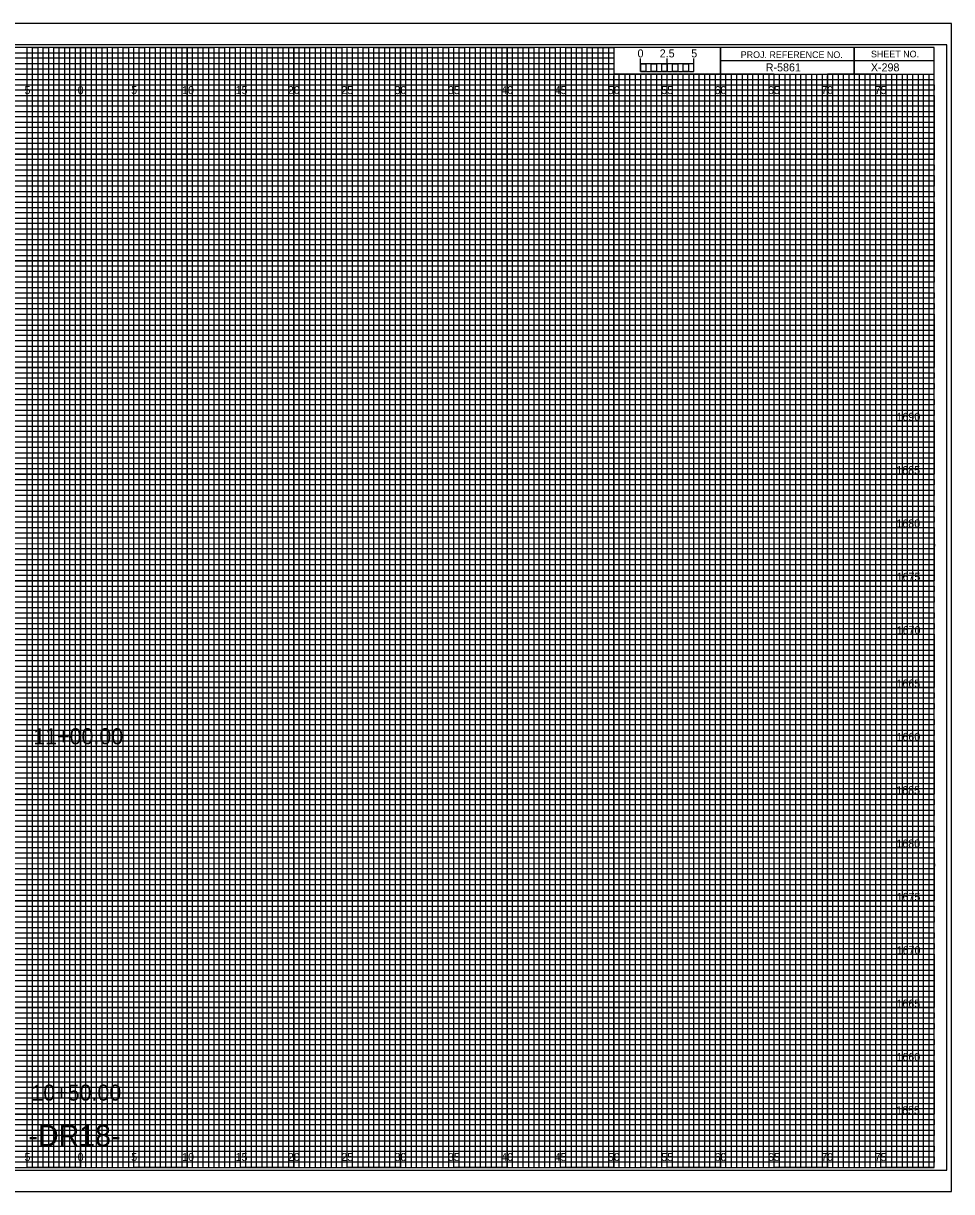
# Model space of a CAD drawing. Extents: x -7 to 162, y -2 to 107.
# Drawn here: x 74.6 to 161.7, y -2.3 to 107.3 of the extents above; entities that cross this region are included whole.
import ezdxf

# ---------------------------------------------------------------- set-up
doc = ezdxf.new("R2010")
doc.units = 0
for name, color, linetype in [('Prop Horizontal Alignment', 7, 'Continuous'), ('Prop XS Alignment Label', 7, 'Continuous'), ('Prop XS Bar Scale Labels', 7, 'Continuous'), ('Prop XS Project Number', 7, 'Continuous'), ('Prop XS Sheet Number', 7, 'Continuous'), ('Raster_Level_0', 7, 'Continuous'), ('Scratch_Level_3', 7, 'Continuous'), ('Sheet Cross Section CELL', 7, 'Continuous'), ('Sheet Cross Section Grid Major CELL', 7, 'Continuous'), ('Sheet Cross Section Grid Middle CELL', 7, 'Continuous'), ('Sheet Cross Section Grid Minor 1 CELL', 7, 'Continuous'), ('Sheet Cross Section Grid Minor 2 CELL', 7, 'Continuous'), ('Sheet Cross Section Scale CELL', 7, 'Continuous'), ('Sheet Cutting Line CELL', 7, 'Continuous'), ('Sheet DOT Grid CELL', 7, 'Continuous'), ('Sheet Plot Border Inside CELL', 7, 'Continuous'), ('Sheet Plot Border Outside CELL', 7, 'Continuous')]:
    doc.layers.add(name, color=color, linetype=linetype)

msp = doc.modelspace()

# ---------------------------------------------------------------- linework, layer by layer
at = {"layer": 'Sheet Cross Section CELL'}
for p, q in [((152.5, 105), (152.5, 102.5)), ((152.5, 102.5), (152.5, 105)), ((160, 103.75), (140, 103.75)), ((140, 103.75), (140, 102.5)), ((140, 102.5), (160, 102.5))]:
    msp.add_line(p, q, dxfattribs=at)
for points in [[(160, 105), (0, 105), (0, 0), (160, 0)], [(140, 105), (130, 105), (130, 102.52), (140, 102.52)], [(160, 105), (140, 105), (140, 102.5), (160, 102.5)]]:
    msp.add_lwpolyline(points, close=True, dxfattribs=at)
at = {"layer": 'Sheet Cross Section Grid Major CELL'}
for p, q in [((75, 105), (70, 105)), ((75, 0), (75, 105)), ((85, 105), (80, 105)), ((80, 105), (80, 0)), ((85, 0), (85, 105)), ((95, 105), (90, 105)), ((90, 105), (90, 0)), ((95, 0), (95, 105)), ((105, 105), (100, 105)), ((100, 105), (100, 0)), ((105, 0), (105, 105)), ((115, 105), (110, 105)), ((110, 105), (110, 0)), ((115, 0), (115, 105)), ((125, 105), (120, 105)), ((120, 105), (120, 0)), ((125, 0), (125, 105)), ((130, 105), (130, 0)), ((135, 0), (135, 102.5)), ((145, 102.5), (140, 102.5)), ((140, 102.5), (140, 0)), ((145, 0), (145, 102.5)), ((155, 102.5), (150, 102.5)), ((150, 102.5), (150, 0)), ((155, 0), (155, 102.5)), ((80, 0), (75, 0)), ((90, 0), (85, 0)), ((100, 0), (95, 0)), ((110, 0), (105, 0)), ((120, 0), (115, 0)), ((130, 0), (125, 0)), ((140, 0), (135, 0)), ((150, 0), (145, 0)), ((160, 0), (155, 0)), ((160, 0), (160, 0))]:
    msp.add_line(p, q, dxfattribs=at)
for points in [[(0, 100), (160, 100), (160, 95), (0, 95)], [(0, 90), (160, 90), (160, 85), (0, 85)], [(0, 80), (160, 80), (160, 75), (0, 75)], [(0, 70), (160, 70), (160, 65), (0, 65)], [(0, 60), (160, 60), (160, 55), (0, 55)], [(0, 50), (160, 50), (160, 45), (0, 45)], [(0, 40), (160, 40), (160, 35), (0, 35)], [(0, 30), (160, 30), (160, 25), (0, 25)], [(0, 20), (160, 20), (160, 15), (0, 15)], [(0, 10), (160, 10), (160, 5), (0, 5)]]:
    msp.add_lwpolyline(points, dxfattribs=at)
at = {"layer": 'Sheet Cross Section Grid Middle CELL'}
for points in [[(72.5, 0), (77.5, 0), (77.5, 105), (82.5, 105), (82.5, 0), (87.5, 0), (87.5, 105), (92.5, 105), (92.5, 0), (97.5, 0), (97.5, 105), (102.5, 105), (102.5, 0), (107.5, 0), (107.5, 105), (112.5, 105), (112.5, 0), (117.5, 0), (117.5, 105), (122.5, 105), (122.5, 0), (127.5, 0), (127.5, 105), (129.97, 105), (130, 105), (130, 102.5), (132.5, 102.5), (132.5, 0), (137.5, 0), (137.5, 102.5), (142.5, 102.5), (142.5, 0), (147.5, 0), (147.5, 102.5), (152.5, 102.5), (152.5, 0), (157.5, 0), (157.5, 102.5)], [(0, 102.5), (137.5, 102.5)], [(0, 92.5), (160, 92.5), (160, 97.5), (0, 97.5)], [(0, 82.5), (160, 82.5), (160, 87.5), (0, 87.5)], [(0, 72.5), (160, 72.5), (160, 77.5), (0, 77.5)], [(0, 62.5), (160, 62.5), (160, 67.5), (0, 67.5)], [(0, 52.5), (160, 52.5), (160, 57.5), (0, 57.5)], [(0, 42.5), (160, 42.5), (160, 47.5), (0, 47.5)], [(0, 32.5), (160, 32.5), (160, 37.5), (0, 37.5)], [(0, 22.5), (160, 22.5), (160, 27.5), (0, 27.5)], [(0, 12.5), (160, 12.5), (160, 17.5), (0, 17.5)], [(0, 2.5), (160, 2.5), (160, 7.5), (0, 7.5)]]:
    msp.add_lwpolyline(points, dxfattribs=at)
at = {"layer": 'Sheet Cross Section Grid Minor 1 CELL'}
for p, q in [((0, 104.5), (130, 104.5)), ((130, 104.5), (130, 103.99)), ((130, 103.99), (0, 103.99)), ((0, 103.5), (130, 103.5)), ((130, 102.95), (0, 102.95)), ((130, 103.5), (130, 102.95)), ((0, 102), (160, 102))]:
    msp.add_line(p, q, dxfattribs=at)
for points in [[(0, 101.5), (135, 101.5), (160, 101.5), (160, 101), (0, 101)], [(0, 100.5), (160, 100.5), (160, 99.5), (0, 99.5)], [(0, 99), (160, 99), (160, 98.5), (0, 98.49)], [(0, 98), (160, 98), (160, 97), (0, 97)], [(0, 96.5), (160, 96.5), (160, 96), (0, 96)], [(0, 95.5), (160, 95.5), (160, 94.5), (0, 94.5)], [(0, 94), (160, 94), (160, 93.5), (0, 93.5)], [(0, 93), (160, 93), (160, 92), (0, 92)], [(0, 91.5), (160, 91.5), (160, 91), (0, 91)], [(0, 90.5), (160, 90.5), (160, 89.5), (0, 89.5)], [(0, 89), (160, 89), (160, 88.5), (0, 88.5)], [(0, 88), (160, 88), (160, 86.98), (160, 86.5), (160, 86), (0, 86)], [(0, 87), (160, 87), (160, 86.5), (0, 86.5)], [(0, 85.5), (160, 85.5), (160, 84.5), (0, 84.52)], [(0, 84.52), (160, 84.5), (160, 84), (0, 84)], [(0, 83.5), (160, 83.5), (160, 83), (0, 83)], [(0, 82), (160, 82), (160, 81.5), (0, 81.5)], [(0, 81), (160, 81), (160, 80.5), (0, 80.5)], [(-0.04, 79.45), (160, 79.45), (160, 78.94), (-0.04, 78.94)], [(0, 78.5), (160, 78.5), (160, 78), (0, 78)], [(0, 77), (160, 77), (160, 76.5), (0, 76.5)], [(0, 76), (160, 76), (160, 75.5), (0, 75.5)], [(0, 74.5), (160, 74.5), (160, 74), (0, 74)], [(0, 73.5), (160, 73.5), (160, 73), (0, 73)], [(0, 72), (160, 72), (160, 71.5), (0, 71.5)], [(0, 71), (160, 71), (160, 70.5), (0, 70.5)], [(0, 69.5), (160, 69.5), (160, 68.99), (0, 69)], [(0, 68.5), (160, 68.5), (160, 68), (0, 68)], [(0, 67), (160, 67), (160, 66.5), (0, 66.5)], [(0, 66), (160, 66), (160, 65.5), (0, 65.5)], [(0, 64.5), (160, 64.5), (160, 64), (0, 64)], [(0, 63.5), (160, 63.5), (160, 63), (0, 63)], [(0, 62), (160, 62), (160, 61.5), (0, 61.5)], [(0, 61), (160, 61), (160, 60.5), (0, 60.5)], [(0, 59.5), (160, 59.5), (160, 59), (0, 59)], [(0, 58.5), (160.03, 58.45), (160, 58), (0, 58)], [(0, 57), (160, 57), (160, 56.5), (0, 56.5)], [(0, 56), (160, 56), (160, 55.5), (0, 55.5)], [(0, 54.5), (160, 54.5), (160, 54), (0, 54)], [(0, 53.5), (160, 53.5), (160, 53), (0, 53)], [(0, 52), (160, 52), (160, 51.5), (0, 51.5)], [(0, 51), (160, 51), (160, 50.5), (0, 50.5)], [(0, 49.5), (160, 49.5), (160, 49), (0, 49)], [(0, 48.5), (160, 48.5), (160, 48), (0, 48)], [(0, 47), (160, 47), (160, 46.5), (0, 46.5)], [(0, 46), (160, 46), (160, 45.5), (0, 45.5)], [(0, 44.5), (160, 44.5), (160, 44), (0, 44)], [(0, 43.5), (160, 43.5), (160, 43), (0, 43)], [(0, 42), (160, 42), (160, 41.5), (0, 41.5)], [(0, 41), (160, 41), (160, 40.5), (0, 40.5)], [(0, 39.5), (160, 39.5), (160, 38.99), (0, 39)], [(0, 38.5), (160, 38.5), (160, 38), (0, 38)], [(0, 37), (160, 37), (160, 36.5), (0, 36.5)], [(0, 36), (160, 36), (160, 35.5), (0, 35.5)], [(0, 34.5), (160, 34.5), (160, 34), (0, 34)], [(0, 33.5), (160, 33.5), (160, 33), (0, 33)], [(0, 32), (160, 32), (160, 31.5), (0, 31.5)], [(0, 31), (160, 31), (160, 30.5), (0, 30.5)], [(0, 29.5), (160, 29.5), (160, 29), (0, 29)], [(0, 28.5), (160.03, 28.46), (160, 28), (0, 28)], [(0, 27), (160, 27), (160, 26.5), (0, 26.5)], [(0, 26), (160, 26), (160, 25.5), (0, 25.5)], [(0, 24.5), (160, 24.5), (160, 24), (0, 24)], [(0, 23.5), (160, 23.5), (160, 23), (0, 23)], [(0, 22), (160, 22), (160, 21.5), (0, 21.5)], [(0, 21), (160, 21), (160, 20.5), (0, 20.5)], [(0, 19.5), (160, 19.5), (160, 19), (0, 19)], [(0, 18.5), (160, 18.5), (160, 18), (0, 18)], [(0, 17), (160, 17), (160, 16.5), (0, 16.5)], [(0, 16), (160, 16), (160, 15.5), (0, 15.5)], [(0, 14.5), (160, 14.5), (160, 14), (0, 14)], [(0, 13.5), (160, 13.5), (160, 13), (0, 13)], [(0, 12), (160, 12), (160, 11.5), (0, 11.5)], [(0, 11), (160, 11), (160, 10.5), (0, 10.5)], [(0, 9.5), (160, 9.5), (160, 9), (0, 9)], [(0, 8.5), (160, 8.5), (160, 8), (0, 8)], [(0, 7), (160, 7), (160, 6.5), (0, 6.5)], [(0, 6), (160, 6), (160, 5.5), (0, 5.5)], [(0, 4.5), (160, 4.5), (160, 4), (0, 4)], [(0, 3.5), (160, 3.5), (160, 3), (0, 3)], [(0, 2), (160, 2), (160, 1.5), (0, 1.5)], [(0, 1), (160, 1), (160, 0.5), (0, 0.5)]]:
    msp.add_lwpolyline(points, dxfattribs=at)
at = {"layer": 'Sheet Cross Section Grid Minor 2 CELL'}
for p, q in [((133.5, 102.5), (133, 102.5)), ((133, 102.5), (133, 0)), ((133.5, 0), (133.5, 102.5)), ((134.5, 102.5), (134, 102.5)), ((134, 102.5), (134, 0)), ((134.5, 0), (134.5, 102.5)), ((133, 0), (132.5, 0)), ((134, 0), (133.5, 0))]:
    msp.add_line(p, q, dxfattribs=at)
for points in [[(75, 0), (75.5, 0), (75.5, 105), (76, 105), (76, 0)], [(76, 0), (76.5, 0), (76.5, 105), (77, 105), (77, 0)], [(77.5, 0), (78, 0), (78, 105), (78.5, 105), (78.5, 0)], [(78.5, 0), (79, 0), (79, 105), (79.5, 105), (79.5, 0)], [(80, 0), (80.5, 0), (80.5, 105), (81, 105), (81, 0)], [(81, 0), (81.5, 0), (81.5, 105), (82, 105), (82, 0)], [(82.5, 0), (83, 0), (83, 105), (83.5, 105), (83.5, 0)], [(83.5, 0), (84, 0), (84, 105), (84.5, 105), (84.5, 0)], [(85, 0), (85.5, 0), (85.5, 105), (86, 105), (86, 0)], [(86, 0), (86.5, 0), (86.5, 105), (87, 105), (87, 0)], [(87.5, 0), (88, 0), (88, 105), (88.5, 105), (88.5, 0)], [(88.5, 0), (89, 0), (89, 105), (89.5, 105), (89.5, 0)], [(90, 0), (90.5, 0), (90.5, 105), (91, 105), (91, 0)], [(91, 0), (91.5, 0), (91.5, 105), (92, 105), (92, 0)], [(92.5, 0), (93, 0), (93, 105), (93.5, 105), (93.5, 0)], [(93.5, 0), (94, 0), (94, 105), (94.5, 105), (94.5, 0)], [(95, 0), (95.5, 0), (95.5, 105), (96, 105), (96, 0)], [(96, 0), (96.5, 0), (96.5, 105), (97, 105), (97, 0)], [(97.5, 0), (98, 0), (98, 105), (98.5, 105), (98.5, 0)], [(98.5, 0), (99, 0), (99, 105), (99.5, 105), (99.5, 0)], [(100, 0), (100.5, 0), (100.5, 105), (101, 105), (101, 0)], [(101, 0), (101.5, 0), (101.5, 105), (102, 105), (102, 0)], [(102.5, 0), (103, 0), (103, 105), (103.5, 105), (103.5, 0)], [(103.5, 0), (104, 0), (104, 105), (104.5, 105), (104.5, 0)], [(105, 0), (105.5, 0), (105.5, 105), (106, 105), (106, 0)], [(106, 0), (106.5, 0), (106.5, 105), (107, 105), (107, 0)], [(107.5, 0), (108, 0), (108, 105), (108.5, 105), (108.5, 0)], [(108.5, 0), (109, 0), (109, 105), (109.5, 105), (109.5, 0)], [(110, 0), (110.5, 0), (110.5, 105), (111, 105), (111, 0)], [(111, 0), (111.5, 0), (111.5, 105), (112, 105), (112, 0)], [(112.5, 0), (113, 0), (113, 105), (113.5, 105), (113.5, 0)], [(113.5, 0), (114, 0), (114, 105), (114.5, 105), (114.5, 0)], [(115, 0), (115.5, 0), (115.5, 105), (116, 105), (116, 0)], [(116, 0), (116.5, 0), (116.5, 105), (117, 105), (117, 0)], [(117.5, 0), (118, 0), (118, 105), (118.5, 105), (118.5, 0)], [(118.5, 0), (119, 0), (119, 105), (119.5, 105), (119.5, 0)], [(120, 0), (120.5, 0), (120.5, 105), (121, 105), (121, 0)], [(121, 0), (121.5, 0), (121.5, 105), (122, 105), (122, 0)], [(122.5, 0), (123, 0), (123, 105), (123.5, 105), (123.5, 0)], [(123.5, 0), (124, 0), (124, 105), (124.5, 105), (124.5, 0)], [(125, 0), (125.5, 0), (125.5, 105), (126, 105), (126, 0)], [(126, 0), (126.5, 0), (126.5, 105), (127, 105), (127, 0)], [(127.5, 0), (128, 0), (128, 105), (128.5, 105), (128.5, 0)], [(128.5, 0), (129, 0), (129, 105), (129.5, 105), (129.5, 0)], [(130, 0), (130.5, 0), (130.5, 102.5), (131.01, 102.5), (131.01, 0)], [(131, 0), (131.5, 0), (131.5, 102.5), (132, 102.5), (132, 0)], [(135, 0), (135.49, 0), (135.49, 102.5), (136, 102.5), (136, 0)], [(136, 0), (136.5, 0), (136.5, 102.5), (137.03, 102.5), (137.03, 0)], [(137.5, 0), (138, 0), (138, 102.5), (138.5, 102.5), (138.5, 0)], [(138.5, 0), (139, 0), (139, 102.5), (139.5, 102.5), (139.5, 0)], [(140, 0), (140.5, 0), (140.5, 102.5), (141, 102.5), (141, 0)], [(141, 0), (141.5, 0), (141.5, 102.5), (142, 102.5), (142, 0)], [(142.5, 0), (143, 0), (143, 102.5), (143.5, 102.5), (143.5, 0)], [(143.5, 0), (144, 0), (144, 102.5), (144.5, 102.5), (144.5, 0)], [(145, 0), (145.5, 0), (145.5, 102.5), (146, 102.5), (146, 0)], [(146, 0), (146.5, 0), (146.5, 102.5), (147, 102.5), (147, 0)], [(147.5, 0), (148, 0), (148, 102.5), (148.5, 102.5), (148.5, 0)], [(148.5, 0), (149, 0), (149, 102.5), (149.5, 102.5), (149.5, 0)], [(150, 0), (150.5, 0), (150.5, 102.5), (151, 102.5), (151, 0)], [(151, 0), (151.5, 0), (151.5, 102.5), (152, 102.5), (152, 0)], [(152.5, 0), (153, 0), (153, 102.5), (153.5, 102.5), (153.5, 0)], [(153.5, 0), (154, 0), (154, 102.5), (154.5, 102.5), (154.5, 0)], [(155, 0), (155.5, 0), (155.5, 102.5), (156, 102.5), (156, 0)], [(156, 0), (156.5, 0), (156.5, 102.5), (157, 102.5), (157, 0)], [(157.5, 0), (158, 0), (158, 102.5), (158.5, 102.5), (158.5, 0)], [(158.5, 0), (159, 0), (159, 102.5), (159.5, 102.5), (159.5, 0)]]:
    msp.add_lwpolyline(points, dxfattribs=at)
at = {"layer": 'Sheet Cross Section Scale CELL'}
for p, q in [((132.5, 102.75), (132.5, 103.95)), ((132.5, 103.45), (132.5, 103.95)), ((135, 102.75), (135, 103.95)), ((137.5, 102.75), (137.5, 103.95)), ((137.5, 103.45), (137.5, 103.95))]:
    msp.add_line(p, q, dxfattribs=at)
for points in [[(137.5, 103.45), (132.5, 103.45), (132.5, 102.75), (137.5, 102.75)], [(132.5, 103.45), (133, 103.45), (133, 102.75), (132.5, 102.75)], [(133.5, 103.45), (134, 103.45), (134, 102.75), (133.5, 102.75)], [(134.5, 103.45), (135, 103.45), (135, 102.75), (134.5, 102.75)], [(135.5, 103.45), (136, 103.45), (136, 102.75), (135.5, 102.75)], [(136.5, 103.45), (137, 103.45), (137, 102.75), (136.5, 102.75)]]:
    msp.add_lwpolyline(points, close=True, dxfattribs=at)
at = {"layer": 'Sheet Cutting Line CELL'}
for p, q in [((161.65, 107.25), (-6.7, 107.25)), ((-6.7, -2.25), (161.65, -2.25))]:
    msp.add_line(p, q, dxfattribs=at)
at = {"layer": 'Sheet DOT Grid CELL'}
for p, q in [((75, 0), (75, 105)), ((80, 0), (80, 105)), ((85, 0), (85, 105)), ((90, 0), (90, 105)), ((95, 0), (95, 105)), ((100, 0), (100, 105)), ((105, 0), (105, 105)), ((110, 0), (110, 105)), ((115, 0), (115, 105)), ((120, 0), (120, 105)), ((125, 0), (125, 105)), ((130, 0), (130, 102.34)), ((135, 0), (135, 102.34)), ((140, 0), (140, 102.34)), ((145, 0), (145, 102.34)), ((150, 0), (150, 102.34)), ((155, 0), (155, 102.34)), ((0, 100), (160, 100)), ((0, 95), (160, 95)), ((0, 90), (160, 90)), ((0, 85), (160, 85)), ((0, 80), (160, 80)), ((0, 75), (160, 75)), ((0, 70), (160, 70)), ((0, 65), (160, 65)), ((0, 60), (160, 60)), ((0, 55), (160, 55)), ((0, 50), (160, 50)), ((0, 45), (160, 45)), ((0, 40), (160, 40)), ((0, 35), (160, 35)), ((0, 30), (160, 30)), ((0, 25), (160, 25)), ((0, 20), (160, 20)), ((0, 15), (160, 15)), ((0, 10), (160, 10)), ((0, 5), (160, 5))]:
    msp.add_line(p, q, dxfattribs=at)
at = {"layer": 'Sheet Plot Border Inside CELL'}
msp.add_lwpolyline([(-5.4, -0.25), (161.2, -0.25), (161.2, 105.25), (-5.4, 105.25)], close=True, dxfattribs=at)
at = {"layer": 'Sheet Plot Border Outside CELL'}
msp.add_lwpolyline([(-6.7, -2.25), (161.65, -2.25), (161.65, 107.25), (-6.7, 107.25)], close=True, dxfattribs=at)

# ---------------------------------------------------------------- texts
at = {"layer": 'Prop Horizontal Alignment'}
for s, p in [('11+00.00', (75.57, 39.68)), ('10+50.00', (75.39, 6.28))]:
    msp.add_text(s, height=1.5, dxfattribs=at).set_placement(p)
at = {"layer": 'Prop XS Alignment Label'}
msp.add_text('-DR18-', height=2, dxfattribs=at).set_placement((75.12, 2))
at = {"layer": 'Prop XS Bar Scale Labels'}
for s, p in [('2.5', (134.29, 104.06)), ('5', (137.24, 104.06))]:
    msp.add_text(s, height=0.75, dxfattribs=at).set_placement(p)
at = {"layer": 'Prop XS Project Number'}
msp.add_text('R-5861', height=0.75, dxfattribs=at).set_placement((144.23, 102.75))
at = {"layer": 'Prop XS Sheet Number'}
msp.add_text('X-298', height=0.75, dxfattribs=at).set_placement((154.08, 102.75))
at = {"layer": 'Raster_Level_0'}
for s, p in [('5', (74.74, 100.62)), ('0', (79.73, 100.62)), ('0', (79.73, 100.62)), ('5', (84.74, 100.62)), ('10', (89.52, 100.62)), ('15', (94.53, 100.62)), ('20', (99.43, 100.62)), ('25', (104.44, 100.62)), ('30', (109.43, 100.62)), ('35', (114.44, 100.62)), ('40', (119.43, 100.62)), ('45', (124.44, 100.62)), ('50', (129.43, 100.62)), ('55', (134.44, 100.62)), ('60', (139.43, 100.62)), ('65', (144.44, 100.62)), ('70', (149.43, 100.62)), ('75', (154.44, 100.62)), ('5', (74.74, 0.62)), ('0', (79.73, 0.62)), ('0', (79.73, 0.62)), ('5', (84.74, 0.62)), ('10', (89.52, 0.62)), ('15', (94.53, 0.62)), ('20', (99.43, 0.62)), ('25', (104.44, 0.62)), ('30', (109.43, 0.62)), ('35', (114.44, 0.62)), ('40', (119.43, 0.62)), ('45', (124.44, 0.62)), ('50', (129.43, 0.62)), ('55', (134.44, 0.62)), ('60', (139.43, 0.62)), ('65', (144.44, 0.62)), ('70', (149.43, 0.62)), ('75', (154.44, 0.62))]:
    msp.add_text(s, height=0.75, dxfattribs=at).set_placement(p)
at = {"layer": 'Scratch_Level_3'}
for s, p in [('1690', (156.48, 70)), ('1685', (156.46, 65)), ('1680', (156.47, 60)), ('1675', (156.49, 55)), ('1670', (156.5, 50)), ('1665', (156.48, 45)), ('1660', (156.48, 40)), ('1685', (156.46, 35)), ('1680', (156.47, 30)), ('1675', (156.49, 25)), ('1670', (156.5, 20)), ('1665', (156.48, 15)), ('1660', (156.48, 10)), ('1655', (156.45, 5))]:
    msp.add_text(s, height=0.75, dxfattribs=at).set_placement(p)
at = {"layer": 'Sheet Cross Section CELL'}
for s, p in [('PROJ. REFERENCE NO.', (141.88, 104)), ('SHEET NO.', (154.09, 104.06))]:
    msp.add_text(s, height=0.625, dxfattribs=at).set_placement(p)
at = {"layer": 'Sheet Cross Section Scale CELL'}
msp.add_text('0', height=0.75, dxfattribs=at).set_placement((132.21, 104.06))

doc.saveas('drawing.dxf')
